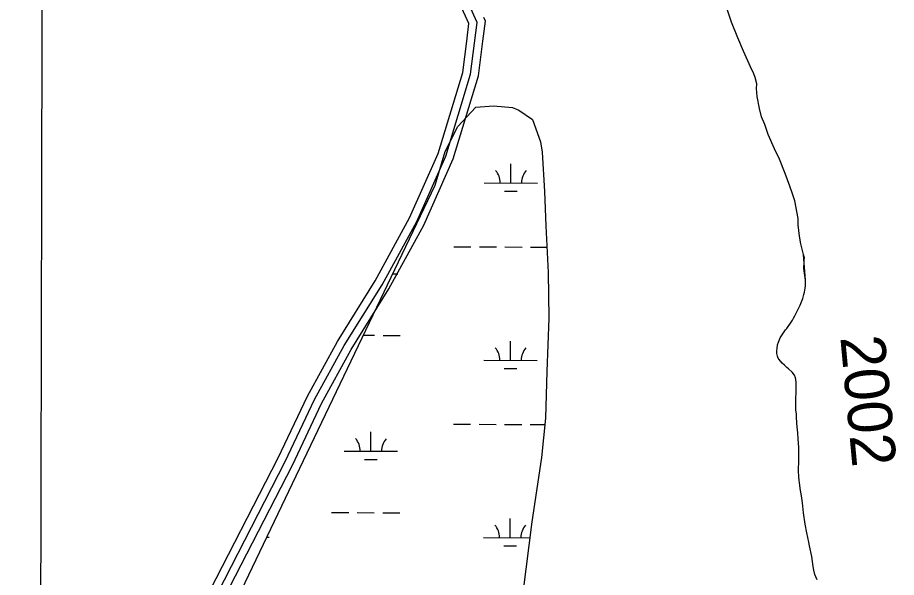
# Model space of a CAD drawing. Extents: x 3192952 to 3230831, y 849296 to 874698.
# Drawn here: x 3207564 to 3209211, y 855775 to 856825 of the extents above; entities that cross this region are included whole.
import ezdxf

# ---------------------------------------------------------------- set-up
doc = ezdxf.new("R2010")
doc.units = 0
for name, color, linetype in [('V-GRID-MAJR', 7, 'Continuous'), ('V-RIVR-IDEN', 7, 'Continuous'), ('V-ROAD-CNTR', 7, 'Continuous'), ('V-SITE-VEGE', 7, 'Continuous'), ('V-TOPO-SHOR', 7, 'Continuous'), ('V-WETL-SWMP', 7, 'Continuous')]:
    doc.layers.add(name, color=color, linetype=linetype)

msp = doc.modelspace()

# ---------------------------------------------------------------- linework, layer by layer
at = {"layer": 'V-GRID-MAJR'}
msp.add_spline([(3207605.4, 854713.5), (3207617.8, 860773), (3207630.1, 866835.5), (3207642.5, 872898.1), (3207642.5, 872901.1)], degree=3, dxfattribs=at)
at = {"layer": 'V-ROAD-CNTR'}
for points in [[(3208405.6, 856780.8), (3208409.8, 856813.9), (3208373.9, 856893.1), (3208307.4, 856949.5), (3208245.9, 856992.7), (3208235.9, 857027.2), (3208211.3, 857086.5), (3208177.5, 857129.7), (3208134.7, 857173.1), (3207916.2, 857309.7), (3207788.1, 857408.9), (3207694.1, 857494.8), (3207623.2, 857571.4), (3207540, 857675.1)], [(3207472.6, 854828.8), (3207571.6, 854971.9), (3207641, 855085.1), (3207720.1, 855229.4), (3207764.5, 855327.3), (3207835.5, 855465), (3207879.3, 855558.7), (3207898.3, 855648.7), (3207926.8, 855722.2), (3208065.6, 855992.7), (3208120.3, 856108.7), (3208176.2, 856210.2), (3208247, 856324), (3208312, 856442.7), (3208366.2, 856565.4), (3208412.9, 856719.3), (3208425.2, 856816.2), (3208386.2, 856902.4)], [(3208435.8, 856780.8), (3208440.6, 856818.5), (3208437.5, 856825.3)], [(3207380.5, 854725.2), (3207460.3, 854837.4), (3207559, 854980.1), (3207628, 855092.7), (3207706.7, 855236.1), (3207751, 855333.9), (3207822.1, 855471.6), (3207865, 855563.5), (3207883.9, 855653), (3207913.1, 855728.4), (3208052.1, 855999.3), (3208107, 856115.5), (3208163.3, 856217.8), (3208234, 856331.6), (3208298.6, 856449.4), (3208352.1, 856570.6), (3208398.2, 856722.5), (3208405.6, 856780.8)], [(3207405, 854707.8), (3207484.8, 854820.2), (3207584.1, 854963.7), (3207654, 855077.6), (3207733.6, 855222.6), (3207778, 855320.8), (3207849, 855458.4), (3207893.6, 855553.9), (3207912.7, 855644.4), (3207940.5, 855716.1), (3208079, 855986.1), (3208133.7, 856101.8), (3208189.2, 856202.6), (3208259.9, 856316.5), (3208325.5, 856436.1), (3208380.3, 856560.1), (3208427.6, 856716.2), (3208435.8, 856780.8)]]:
    msp.add_lwpolyline(points, dxfattribs=at)
at = {"layer": 'V-SITE-VEGE'}
for p, q in [((3208902.2, 856816.5), (3208887.9, 856858.8)), ((3208913.9, 856787.3), (3208902.2, 856816.5)), ((3208924.3, 856762.2), (3208913.9, 856787.3)), ((3208937.4, 856733), (3208924.3, 856762.2)), ((3208943.9, 856719.8), (3208937.4, 856733)), ((3208946.5, 856713.1), (3208943.9, 856719.8)), ((3208949.1, 856701.2), (3208946.5, 856713.1)), ((3208949, 856692), (3208949.1, 856701.2)), ((3208950.2, 856677.4), (3208949, 856692)), ((3208954.1, 856654.9), (3208950.2, 856677.4)), ((3208957.9, 856639.1), (3208954.1, 856654.9)), ((3208964.4, 856624.5), (3208957.9, 856639.1)), ((3208970.9, 856605.9), (3208964.4, 856624.5)), ((3208982.7, 856579.4), (3208970.9, 856605.9)), ((3208991.8, 856559.6), (3208982.7, 856579.4)), ((3209002.2, 856533.1), (3208991.8, 856559.6)), ((3209011.3, 856509.2), (3209002.2, 856533.1)), ((3209016.5, 856494.7), (3209011.3, 856509.2)), ((3209020.4, 856481.4), (3209016.5, 856494.7)), ((3209026.8, 856448.4), (3209020.4, 856481.4)), ((3209026.7, 856436.5), (3209026.8, 856448.4)), ((3209029.2, 856415.3), (3209026.7, 856436.5)), ((3209031.8, 856400.8), (3209029.2, 856415.3)), ((3209037, 856380.9), (3209031.8, 856400.8)), ((3209040.5, 856333), (3209037, 856380.9)), ((3209040.4, 856322.4), (3209040.5, 856333)), ((3209037.8, 856305.7), (3209038.8, 856310.6)), ((3209038.8, 856310.6), (3209040, 856318)), ((3209040, 856318), (3209040.4, 856322.4)), ((3209030.8, 856286.2), (3209035.6, 856298.5)), ((3209035.6, 856298.5), (3209037.8, 856305.7)), ((3209025.5, 856275.9), (3209028.2, 856281)), ((3209028.2, 856281), (3209030.8, 856286.2)), ((3209016, 856257.7), (3209018.2, 856261.8)), ((3209018.2, 856261.8), (3209020.7, 856266)), ((3209020.7, 856266), (3209025.5, 856275.9)), ((3209005.5, 856242.4), (3209013.6, 856254)), ((3209013.6, 856254), (3209016, 856257.7)), ((3208993.3, 856224.7), (3209000.6, 856236.2)), ((3209000.6, 856236.2), (3209003.2, 856239.8)), ((3209003.2, 856239.8), (3209005.5, 856242.4)), ((3208988.4, 856211.3), (3208989.8, 856216.7)), ((3208989.8, 856216.7), (3208993.3, 856224.7)), ((3208986.9, 856201.2), (3208987.2, 856204.9)), ((3208987.1, 856195.3), (3208986.9, 856201.2)), ((3208988.2, 856190.2), (3208987.1, 856195.3)), ((3208987.2, 856204.9), (3208988.4, 856211.3)), ((3208989.6, 856186.7), (3208988.2, 856190.2)), ((3208991.3, 856184), (3208989.6, 856186.7)), ((3208997.1, 856177.3), (3208991.3, 856184)), ((3209001, 856173.4), (3208997.1, 856177.3)), ((3209005.8, 856169.3), (3209001, 856173.4)), ((3209008.7, 856166.5), (3209005.8, 856169.3)), ((3209015.9, 856160.2), (3209008.7, 856166.5)), ((3209019.9, 856154.6), (3209015.9, 856160.2)), ((3209022.1, 856149.9), (3209019.9, 856154.6)), ((3209022.8, 856146.3), (3209022.1, 856149.9)), ((3209023.4, 856140.7), (3209022.8, 856146.3)), ((3209023.3, 856128.8), (3209023.4, 856140.7)), ((3209022.5, 856104.6), (3209022.8, 856114.4)), ((3209022.8, 856114.4), (3209023.2, 856118.3)), ((3209023, 856124.3), (3209023.3, 856128.8)), ((3209023.2, 856118.3), (3209023, 856124.3)), ((3209022.7, 856100.5), (3209022.5, 856104.6)), ((3209022.6, 856093.9), (3209022.7, 856100.5)), ((3209022.8, 856089.2), (3209022.6, 856093.9)), ((3209023.5, 856082), (3209022.8, 856089.2)), ((3209023.7, 856076.7), (3209023.5, 856082)), ((3209024.6, 856064.7), (3209023.7, 856076.7)), ((3209024.9, 856057.6), (3209024.6, 856064.7)), ((3209026.2, 856046.5), (3209024.9, 856057.6)), ((3209027.1, 856035.4), (3209026.2, 856046.5)), ((3209028, 856018.8), (3209027.1, 856035.4)), ((3209028.1, 856013.9), (3209028, 856018.8)), ((3209027.9, 856006.3), (3209028.1, 856013.9)), ((3209028, 855994.7), (3209027.9, 856006.3)), ((3209027.7, 855976.1), (3209028, 855994.7)), ((3209028.4, 855963.5), (3209027.7, 855976.1)), ((3209028.9, 855957.8), (3209028.4, 855963.5)), ((3209029.6, 855952.5), (3209028.9, 855957.8)), ((3209031.1, 855938.1), (3209029.6, 855952.5)), ((3209032.4, 855932.2), (3209031.1, 855938.1)), ((3209033.9, 855923.7), (3209032.4, 855932.2)), ((3209035, 855915.5), (3209033.9, 855923.7)), ((3209036.7, 855896.7), (3209035, 855915.5)), ((3209040.2, 855874.9), (3209036.7, 855896.7)), ((3209043, 855858.9), (3209040.2, 855874.9)), ((3209046.6, 855841.5), (3209043, 855858.9)), ((3209048.3, 855834.3), (3209046.6, 855841.5)), ((3209052.5, 855814.6), (3209048.3, 855834.3)), ((3209055.1, 855795.6), (3209052.5, 855814.6)), ((3209056.2, 855789), (3209055.1, 855795.6)), ((3209058.3, 855780.8), (3209056.2, 855789)), ((3209059.8, 855776.3), (3209058.3, 855780.8)), ((3209062.5, 855770.8), (3209059.8, 855776.3))]:
    msp.add_line(p, q, dxfattribs=at)
at = {"layer": 'V-TOPO-SHOR'}
for points in [[(3209037, 856380.9), (3209031.8, 856400.8), (3209029.2, 856415.3), (3209026.7, 856436.5), (3209026.8, 856448.4), (3209020.4, 856481.4), (3209016.5, 856494.7), (3209011.3, 856509.2), (3209002.2, 856533.1), (3208991.8, 856559.6), (3208982.7, 856579.4), (3208970.9, 856605.9), (3208964.4, 856624.5), (3208957.9, 856639.1), (3208954.1, 856654.9), (3208950.2, 856677.4), (3208949, 856692), (3208949.1, 856701.2), (3208946.5, 856713.1), (3208943.9, 856719.8), (3208937.4, 856733), (3208924.3, 856762.2), (3208913.9, 856787.3), (3208902.2, 856816.5), (3208887.9, 856858.8)], [(3209026.2, 856046.5), (3209024.9, 856057.6), (3209024.6, 856064.7), (3209023.7, 856076.7), (3209023.5, 856082), (3209022.8, 856089.2), (3209022.6, 856093.9), (3209022.7, 856100.5), (3209022.5, 856104.6), (3209022.8, 856114.4), (3209023.2, 856118.3), (3209023, 856124.3), (3209023.3, 856128.8), (3209023.4, 856140.7), (3209022.8, 856146.3), (3209022.1, 856149.9), (3209019.9, 856154.5), (3209015.9, 856160.2), (3209008.7, 856166.5), (3209005.8, 856169.3), (3209001, 856173.4), (3208997.1, 856177.3), (3208991.3, 856184), (3208989.6, 856186.7), (3208988.2, 856190.2), (3208987.1, 856195.3), (3208986.9, 856201.2), (3208987.2, 856204.9), (3208988.4, 856211.3), (3208989.8, 856216.7), (3208993.3, 856224.7), (3209000.6, 856236.2), (3209003.2, 856239.8), (3209005.5, 856242.4), (3209013.6, 856254), (3209016, 856257.7), (3209018.2, 856261.8), (3209020.7, 856266), (3209025.5, 856275.9), (3209028.2, 856281), (3209030.8, 856286.2), (3209035.6, 856298.5), (3209037.8, 856305.7), (3209038.8, 856310.6), (3209040, 856318), (3209040.4, 856322.4), (3209040.5, 856333), (3209037.3, 856354.4), (3209038.4, 856366.7), (3209038.4, 856371.4), (3209038.6, 856374.5), (3209037, 856380.9)], [(3209062.5, 855770.8), (3209059.8, 855776.3), (3209058.3, 855780.8), (3209056.2, 855789), (3209055.1, 855795.6), (3209052.5, 855814.6), (3209048.3, 855834.3), (3209046.6, 855841.5), (3209043, 855858.9), (3209040.2, 855874.9), (3209036.7, 855896.7), (3209035, 855915.5), (3209033.9, 855923.7), (3209032.4, 855932.2), (3209031.1, 855938.1), (3209029.6, 855952.5), (3209028.9, 855957.8), (3209028.4, 855963.5), (3209027.7, 855976.1), (3209028, 855994.7), (3209027.9, 856006.3), (3209028.1, 856013.9), (3209028, 856018.8), (3209027.1, 856035.4), (3209026.2, 856046.5)]]:
    msp.add_lwpolyline(points, dxfattribs=at)
at = {"layer": 'V-WETL-SWMP'}
for p, q in [((3208388.9, 856621.1), (3208422.6, 856657.3)), ((3208422.6, 856657.3), (3208456.1, 856660)), ((3208456.1, 856660), (3208491.5, 856656.8)), ((3208491.5, 856656.8), (3208503.3, 856651.8)), ((3208503.3, 856651.8), (3208528.7, 856633.9)), ((3208528.7, 856633.9), (3208544.2, 856592.5)), ((3208365, 856574.1), (3208388.9, 856621.1)), ((3208544.2, 856592.5), (3208547, 856572.8)), ((3208346.8, 856511.2), (3208365, 856574.1)), ((3208547, 856572.8), (3208551.4, 856499)), ((3208488.4, 856515.1), (3208488.4, 856551.1)), ((3207732.9, 855226.8), (3208346.8, 856511.2)), ((3208438.4, 856515.2), (3208538.4, 856515)), ((3208476.3, 856499.7), (3208500.3, 856499.7)), ((3208551.4, 856499), (3208553.9, 856435)), ((3208553.9, 856435), (3208558.2, 856347.4)), ((3208381.3, 856395.3), (3208413.3, 856395.2)), ((3208429.3, 856395.2), (3208461.3, 856395.1)), ((3208477.3, 856395.1), (3208509.3, 856395)), ((3208525.3, 856395), (3208555.9, 856394.9)), ((3208267.3, 856344.7), (3208276.6, 856344.7)), ((3208558.2, 856347.4), (3208559.6, 856261.8)), ((3208559.6, 856261.8), (3208555.9, 856161.5)), ((3208212.1, 856229.4), (3208233, 856229.4)), ((3208249, 856229.3), (3208281, 856229.3)), ((3208487.7, 856182.5), (3208487.8, 856218.5)), ((3208437.7, 856182.6), (3208537.7, 856182.4)), ((3208475.7, 856167), (3208499.7, 856167)), ((3208555.9, 856161.5), (3208553.3, 856074)), ((3208553.3, 856074), (3208545.9, 856000.2)), ((3208226, 856012.1), (3208226, 856048.1)), ((3208380.7, 856062.6), (3208412.7, 856062.5)), ((3208428.7, 856062.5), (3208460.7, 856062.4)), ((3208476.7, 856062.4), (3208508.7, 856062.3)), ((3208524.7, 856062.3), (3208552.2, 856062.3)), ((3208176, 856012.2), (3208276, 856012)), ((3208545.9, 856000.2), (3208527.4, 855879.4)), ((3208214, 855996.7), (3208238, 855996.7)), ((3208152.4, 855896.8), (3208184.4, 855896.8)), ((3208200.4, 855896.8), (3208232.4, 855896.7)), ((3208248.4, 855896.7), (3208280.4, 855896.6)), ((3208487.1, 855849.8), (3208487.2, 855885.8)), ((3208527.4, 855879.4), (3208510.7, 855746.7)), ((3208031.1, 855850.6), (3208035.2, 855850.6)), ((3208437.1, 855849.9), (3208523.7, 855849.7)), ((3208475.1, 855834.4), (3208499.1, 855834.3))]:
    msp.add_line(p, q, dxfattribs=at)
for centre, start, end in [((3208433.1, 856515.7), 359.1198, 40.6635), ((3208543.6, 856515.5), 139.1198, 180.6635), ((3208432.5, 856183), 359.1198, 40.6635), ((3208543, 856182.8), 139.1198, 180.6635), ((3208170.7, 856012.7), 359.1198, 40.6635), ((3208281.2, 856012.5), 139.1198, 180.6635), ((3208431.9, 855850.4), 359.1198, 40.6635), ((3208542.4, 855850.2), 139.1198, 180.6635)]:
    msp.add_arc(centre, 35.2, start, end, dxfattribs=at)

# ---------------------------------------------------------------- texts
at = {"layer": 'V-RIVR-IDEN'}
msp.add_text('2002', height=83, rotation=275.3714, dxfattribs=at).set_placement((3209105.8, 856225.8))

doc.saveas('drawing.dxf')
